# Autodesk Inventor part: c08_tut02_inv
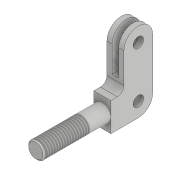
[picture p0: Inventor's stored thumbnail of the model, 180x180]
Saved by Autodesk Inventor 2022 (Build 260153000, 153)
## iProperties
Created: 2015-03
Part Number: c08_tut02_inv
Material: Generic
Document SubType Name: Modeling
Designer: Sandeep
Density: 1 g/cm^3
Appearance: Default
Author: Sandeep
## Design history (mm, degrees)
sketch "Sketch1"
  geometry: L1 (0, 0)-(0, 22); L2 (0, 22)-(5, 22); L3 (10, 27)-(10, 50); L4 (32, 50)-(32, 11); L5 (21, 0)-(0, 0); A1 r 11 centre (21, 50) between (32, 50) and (10, 50); A2 r 11 centre (21, 11) between (21, 0) and (32, 11); A3 r 5 centre (5, 27) between (5, 22) and (10, 27)
  constraints: 10 end point, 6 point on circle, 6 tangent, 3 centre point, 3 perpendicular, 1 parallel, 1 vertical
  dimensions: "d0" = 11 radius of A1; "d1" = 11 radius of A2; "d2" = 5 radius of A3; "d3" = 32 distance between parallel lines of L1 L4; "d4" = 22 distance between parallel lines of L5 L2; "d5" = 50 distance from line of A1.centre L5
extrude "Extrusion1" new body sketch "Sketch1" stored distance "d6" = 13; taper "d7" = 0 deg
hole "Hole1" diameter "d10" = 8; stored, may be unused: countersink angle "d14" = 90 deg, drill point angle "d16" = 118 deg; dims "d8" = 10, "d9" = 10, "d11" = 6, "d12" = 4, "d13" = 2, "d15" = 8
hole "Hole2" diameter "d19" = 8; stored, may be unused: countersink angle "d23" = 90 deg, drill point angle "d25" = 118 deg; dims "d17" = 10, "d18" = 10, "d20" = 6, "d21" = 4, "d22" = 2, "d24" = 8
sketch "Sketch2"
  geometry: L1 (0, -11)-(13, -11) reference; L2 (4, -11)-(4, 20); L3 (4, 20)-(9, 20); L4 (9, 20)-(9, -11); L5 (6.5, 50)-(6.5, -21.602); L6 (13, 50)-(0, 50) reference; L7 (9, -11)-(4, -11)
  constraints: 10 end point, 2 perpendicular, 2 point on line, 2 vertical, 1 collinear, 1 other
  dimensions: "d26" = 5 distance between parallel lines of L4 L2; "d27" = 30 distance between parallel lines of L6 L3
extrude "Extrusion2" cut sketch "Sketch2" extent not by distance; stored distance "d28" = 13; taper "d29" = 0 deg
sketch "Sketch3"
  geometry: L1 (13, 0)-(0, 0) reference; L2 (6.5, 0)-(6.5, 35.061); C1 r 6.5 at (6.5, 11)
  constraints: 2 end point, 1 centre point, 1 point on line, 1 vertical
  dimensions: "d30" = 13 diameter of C1; "d31" = 11 distance from line of C1.centre L1
extrude "Extrusion3" join sketch "Sketch3" distance "d32" = 51; taper "d33" = 0 deg
chamfer "Chamfer1" distance "d34" = 1; stored, may be unused: second distance "d35" = 2, angle "d36" = 45 deg
thread "Thread1" dims "d37" = 34, "d38" = 0
body "Solid1"
